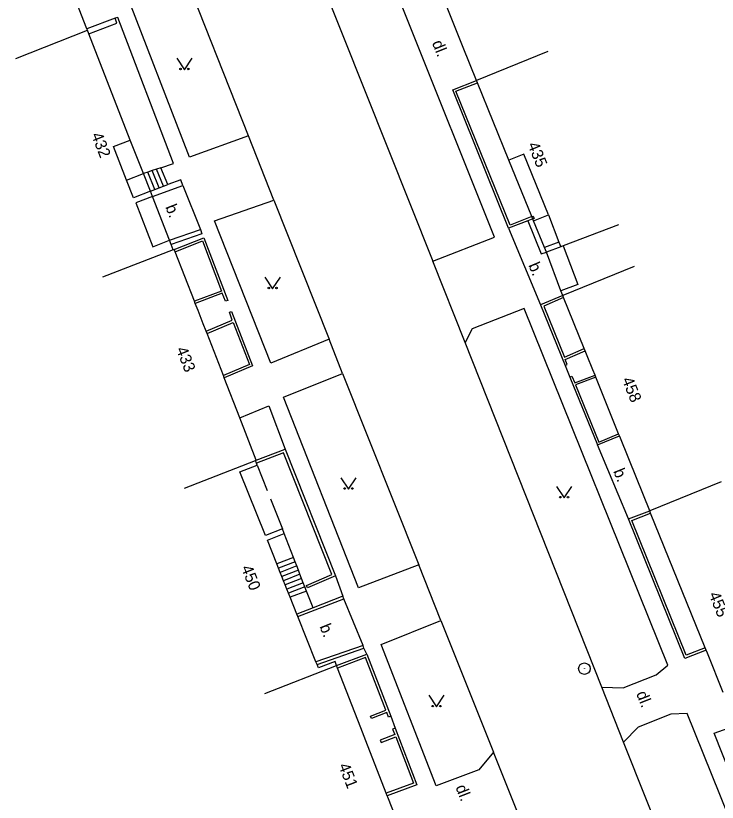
# Model space of a CAD drawing. Extents: x -577457 to -568404, y -1208466 to -1201387.
# Drawn here: x -575242.8 to -575197.2, y -1204609.6 to -1204558.5 of the extents above; entities that cross this region are included whole.
import ezdxf

# ---------------------------------------------------------------- set-up
doc = ezdxf.new("R2010")
doc.units = 0
for name, color, linetype in [('BUDOVY_MĚŘ', 7, 'Continuous'), ('MAP_ZN_BP', 7, 'Continuous'), ('POMOC_POPIS', 7, 'Continuous'), ('ROZHRANÍ_PLOCH', 7, 'Continuous'), ('ZN_DOPLŇKOVÉ', 7, 'Continuous'), ('ZN_KULTUR', 7, 'Continuous'), ('Č_POPIS_ORIENT', 7, 'Continuous')]:
    doc.layers.add(name, color=color, linetype=linetype)

msp = doc.modelspace()

# ---------------------------------------------------------------- linework, layer by layer
at = {"layer": 'BUDOVY_MĚŘ'}
for points in [[(-575238.17, -1204559.36), (-575238.83, -1204557.68)], [(-575242.79, -1204561.27), (-575238.14, -1204559.45)], [(-575238.14, -1204559.45), (-575238.17, -1204559.36)], [(-575238.05, -1204559.67), (-575238.14, -1204559.45)], [(-575235.35, -1204566.57), (-575238.05, -1204559.67)], [(-575212.88, -1204562.71), (-575213.74, -1204560.57)], [(-575208.25, -1204560.83), (-575212.88, -1204562.71)], [(-575212.82, -1204562.86), (-575212.88, -1204562.71)], [(-575210.78, -1204567.87), (-575212.82, -1204562.86)], [(-575234.5, -1204568.75), (-575235.35, -1204566.57)], [(-575209.28, -1204571.54), (-575210.78, -1204567.87)], [(-575234.05, -1204569.89), (-575234.5, -1204568.75)], [(-575233.92, -1204570.23), (-575234.05, -1204569.89)], [(-575232.8, -1204573.08), (-575233.92, -1204570.23)], [(-575209.22, -1204571.69), (-575209.28, -1204571.54)], [(-575209.17, -1204571.81), (-575209.22, -1204571.69)], [(-575208.47, -1204573.54), (-575209.17, -1204571.81)], [(-575203.66, -1204572.08), (-575207.24, -1204573.44)], [(-575232.69, -1204573.36), (-575232.8, -1204573.08)], [(-575232.56, -1204573.69), (-575232.69, -1204573.36)], [(-575207.24, -1204573.44), (-575207.41, -1204573.51)], [(-575232.56, -1204573.69), (-575237.16, -1204575.48)], [(-575232.5, -1204573.67), (-575232.56, -1204573.69)], [(-575232.44, -1204573.82), (-575232.5, -1204573.67)], [(-575231.19, -1204577.03), (-575232.44, -1204573.82)], [(-575208.34, -1204573.86), (-575208.47, -1204573.54)], [(-575207.41, -1204573.51), (-575208.34, -1204573.86)], [(-575207.39, -1204576.36), (-575208.34, -1204573.86)], [(-575202.64, -1204574.78), (-575207.28, -1204576.66)], [(-575207.28, -1204576.66), (-575207.39, -1204576.36)], [(-575231.13, -1204577.18), (-575231.19, -1204577.03)], [(-575207.22, -1204576.8), (-575207.28, -1204576.66)], [(-575205.88, -1204580.11), (-575207.22, -1204576.8)], [(-575230.95, -1204577.64), (-575231.13, -1204577.18)], [(-575230.43, -1204578.97), (-575230.62, -1204578.5)], [(-575230.37, -1204579.12), (-575230.43, -1204578.97)], [(-575229.31, -1204581.85), (-575230.37, -1204579.12)], [(-575205.82, -1204580.25), (-575205.88, -1204580.11)], [(-575205.69, -1204580.58), (-575205.82, -1204580.25)], [(-575205.18, -1204581.84), (-575205.32, -1204581.48)], [(-575229.25, -1204582), (-575229.31, -1204581.85)], [(-575205.13, -1204581.97), (-575205.18, -1204581.84)], [(-575203.65, -1204585.63), (-575205.13, -1204581.97)], [(-575227.17, -1204587.35), (-575228.24, -1204584.61)], [(-575203.59, -1204585.77), (-575203.65, -1204585.63)], [(-575203.53, -1204585.93), (-575203.59, -1204585.77)], [(-575231.83, -1204589.17), (-575227.23, -1204587.37)], [(-575225.48, -1204591.8), (-575226.58, -1204592.24), (-575228.23, -1204588.11), (-575227.11, -1204587.68)], [(-575227.23, -1204587.37), (-575227.17, -1204587.35)], [(-575227.16, -1204587.54), (-575227.23, -1204587.37)], [(-575227.11, -1204587.68), (-575227.16, -1204587.54)], [(-575201.63, -1204590.63), (-575202.49, -1204588.5)], [(-575196.99, -1204588.75), (-575201.63, -1204590.63)], [(-575201.57, -1204590.78), (-575201.63, -1204590.63)], [(-575198.03, -1204599.53), (-575201.57, -1204590.78)], [(-575225.36, -1204592.11), (-575225.48, -1204591.8)], [(-575225.84, -1204594.08), (-575226.45, -1204592.55), (-575225.36, -1204592.11)], [(-575225.73, -1204594.36), (-575225.84, -1204594.08)], [(-575225.62, -1204594.63), (-575225.73, -1204594.36)], [(-575225.52, -1204594.9), (-575225.62, -1204594.63)], [(-575225.41, -1204595.17), (-575225.52, -1204594.9)], [(-575225.3, -1204595.44), (-575225.41, -1204595.17)], [(-575225.19, -1204595.71), (-575225.3, -1204595.44)], [(-575225.08, -1204595.98), (-575225.19, -1204595.71)], [(-575224.97, -1204596.25), (-575225.08, -1204595.98)], [(-575224.53, -1204597.34), (-575224.97, -1204596.25)], [(-575224.47, -1204597.5), (-575224.53, -1204597.34)], [(-575197.96, -1204599.69), (-575198.03, -1204599.53)], [(-575197.88, -1204599.88), (-575197.96, -1204599.69)], [(-575223.23, -1204600.6), (-575223.3, -1204600.43)], [(-575221.96, -1204600.68), (-575222.06, -1204600.41), (-575223.14, -1204600.83), (-575223.23, -1204600.6)], [(-575226.62, -1204602.49), (-575221.96, -1204600.68)], [(-575221.9, -1204600.84), (-575221.96, -1204600.68)], [(-575220.39, -1204604.71), (-575221.9, -1204600.84)], [(-575218.73, -1204608.97), (-575220.06, -1204605.57)], [(-575218.67, -1204609.13), (-575218.73, -1204608.97)], [(-575218.63, -1204609.23), (-575218.67, -1204609.13)]]:
    msp.add_lwpolyline(points, dxfattribs=at)
at = {"layer": 'MAP_ZN_BP'}
for radius in [0.375, 0.0005]:
    msp.add_circle((-575205.87, -1204600.88), radius, dxfattribs=at)
at = {"layer": 'ROZHRANÍ_PLOCH'}
for points in [[(-575215.71, -1204574.44), (-575211.71, -1204572.88), (-575217.35, -1204558.78), (-575226.55, -1204535.73), (-575227.92, -1204533.66)], [(-575231.17, -1204535.5), (-575224.5, -1204552.39), (-575215.71, -1204574.44)], [(-575227.68, -1204566.31), (-575231.5, -1204567.69), (-575235.77, -1204556.62), (-575232.12, -1204555.08)], [(-575227.68, -1204566.31), (-575232.12, -1204555.08)], [(-575233.36, -1204568.37), (-575232.54, -1204568.1), (-575236.16, -1204558.62), (-575236.33, -1204558.67)], [(-575226.03, -1204570.47), (-575227.68, -1204566.31)], [(-575233.36, -1204568.37), (-575233.64, -1204568.46)], [(-575232.91, -1204569.46), (-575233.36, -1204568.37)], [(-575234.21, -1204568.65), (-575234.5, -1204568.75)], [(-575233.93, -1204568.56), (-575234.21, -1204568.65)], [(-575233.75, -1204569.78), (-575234.21, -1204568.65)], [(-575233.64, -1204568.46), (-575233.93, -1204568.56)], [(-575233.47, -1204569.67), (-575233.93, -1204568.56)], [(-575233.19, -1204569.57), (-575233.64, -1204568.46)], [(-575234.05, -1204569.89), (-575233.75, -1204569.78)], [(-575233.75, -1204569.78), (-575233.47, -1204569.67)], [(-575233.47, -1204569.67), (-575233.19, -1204569.57)], [(-575233.19, -1204569.57), (-575232.91, -1204569.46)], [(-575231.95, -1204569.52), (-575230.8, -1204572.37)], [(-575222.43, -1204579.5), (-575226.23, -1204581.06), (-575229.89, -1204571.82), (-575226.03, -1204570.47)], [(-575226.03, -1204570.47), (-575222.43, -1204579.5)], [(-575209.54, -1204571.81), (-575208.67, -1204573.95), (-575208.34, -1204573.86)], [(-575210.79, -1204572.29), (-575208.71, -1204577.27)], [(-575213.61, -1204579.72), (-575215.71, -1204574.44)], [(-575204.74, -1204602.07), (-575203.36, -1204602.12), (-575201.22, -1204601.27), (-575200.45, -1204600.65), (-575209.79, -1204577.5), (-575213.16, -1204578.82), (-575213.61, -1204579.72)], [(-575221.57, -1204581.73), (-575222.43, -1204579.5)], [(-575204.74, -1204602.07), (-575213.61, -1204579.72)], [(-575216.61, -1204594.14), (-575220.54, -1204595.64), (-575225.41, -1204583.25), (-575221.57, -1204581.73)], [(-575221.57, -1204581.73), (-575216.61, -1204594.14)], [(-575228.24, -1204584.61), (-575226.35, -1204583.82), (-575225.3, -1204586.64)], [(-575203.01, -1204591.16), (-575205.01, -1204586.36)], [(-575227.11, -1204587.68), (-575226.46, -1204589.32)], [(-575226.25, -1204589.86), (-575225.48, -1204591.8)], [(-575224.76, -1204593.66), (-575225.36, -1204592.11)], [(-575224.76, -1204593.66), (-575225.84, -1204594.08)], [(-575224.65, -1204593.94), (-575224.76, -1204593.66)], [(-575224.65, -1204593.94), (-575225.73, -1204594.36)], [(-575224.55, -1204594.21), (-575225.62, -1204594.63)], [(-575224.55, -1204594.21), (-575224.65, -1204593.94)], [(-575224.44, -1204594.48), (-575224.55, -1204594.21)], [(-575215.19, -1204597.75), (-575216.61, -1204594.14)], [(-575224.44, -1204594.48), (-575225.52, -1204594.9)], [(-575224.34, -1204594.75), (-575225.41, -1204595.17)], [(-575224.34, -1204594.75), (-575224.44, -1204594.48)], [(-575224.23, -1204595.02), (-575224.34, -1204594.75)], [(-575222.04, -1204594.85), (-575221.56, -1204596.18)], [(-575224.23, -1204595.02), (-575225.3, -1204595.44)], [(-575224.12, -1204595.3), (-575225.19, -1204595.71)], [(-575224.12, -1204595.3), (-575224.23, -1204595.02)], [(-575224.02, -1204595.57), (-575224.12, -1204595.3)], [(-575224.02, -1204595.57), (-575225.08, -1204595.98)], [(-575223.91, -1204595.84), (-575224.97, -1204596.25)], [(-575223.91, -1204595.84), (-575224.02, -1204595.57)], [(-575223.49, -1204596.93), (-575223.91, -1204595.84)], [(-575220.24, -1204599.38), (-575221.49, -1204596.35)], [(-575211.78, -1204606.3), (-575212.73, -1204607.45), (-575215.49, -1204608.49), (-575219.07, -1204599.32), (-575215.19, -1204597.75)], [(-575215.19, -1204597.75), (-575211.78, -1204606.3)], [(-575220, -1204599.93), (-575220.18, -1204599.55)], [(-575203.33, -1204605.65), (-575204.74, -1204602.07)], [(-575194.92, -1204614.42), (-575199.19, -1204603.8), (-575200.25, -1204603.84), (-575202.37, -1204604.68), (-575203.33, -1204605.65)], [(-575192.89, -1204631.84), (-575203.33, -1204605.65)], [(-575210.25, -1204610.08), (-575211.78, -1204606.3)]]:
    msp.add_lwpolyline(points, dxfattribs=at)
at = {"layer": 'ZN_DOPLŇKOVÉ'}
for points in [[(-575213.74, -1204560.57), (-575214.78, -1204557.97)], [(-575236.33, -1204558.67), (-575238.17, -1204559.36)], [(-575238.05, -1204559.67), (-575236.22, -1204558.98), (-575236.33, -1204558.67)], [(-575210.79, -1204572.29), (-575214.42, -1204563.32), (-575212.88, -1204562.71)], [(-575209.28, -1204571.54), (-575210.7, -1204572.09), (-575214.21, -1204563.41), (-575212.82, -1204562.86)], [(-575235.6, -1204569.18), (-575236.45, -1204567), (-575235.35, -1204566.57)], [(-575208.2, -1204571.42), (-575209.81, -1204567.48), (-575210.78, -1204567.87)], [(-575235.6, -1204569.18), (-575234.5, -1204568.75)], [(-575234.05, -1204569.89), (-575235.15, -1204570.32), (-575235.6, -1204569.18)], [(-575231.95, -1204569.52), (-575232.08, -1204569.16), (-575232.91, -1204569.46)], [(-575233.92, -1204570.23), (-575231.95, -1204569.52)], [(-575233.92, -1204570.23), (-575235, -1204570.65), (-575233.88, -1204573.5), (-575232.8, -1204573.08)], [(-575209.17, -1204571.81), (-575208.2, -1204571.42)], [(-575208.2, -1204571.42), (-575207.53, -1204573.19)], [(-575209.54, -1204571.81), (-575210.79, -1204572.29)], [(-575209.22, -1204571.69), (-575209.54, -1204571.81)], [(-575209.28, -1204571.54), (-575209.2, -1204571.51), (-575209.14, -1204571.66), (-575209.22, -1204571.69)], [(-575232.8, -1204573.08), (-575230.8, -1204572.37)], [(-575230.8, -1204572.37), (-575230.7, -1204572.65), (-575232.69, -1204573.36)], [(-575232.5, -1204573.67), (-575230.57, -1204572.92), (-575229.03, -1204576.98), (-575229.18, -1204577.03), (-575229.38, -1204576.52), (-575231.13, -1204577.18)], [(-575232.44, -1204573.82), (-575230.67, -1204573.12), (-575229.43, -1204576.37), (-575231.19, -1204577.03)], [(-575207.53, -1204573.19), (-575208.47, -1204573.54)], [(-575207.53, -1204573.19), (-575207.41, -1204573.51)], [(-575207.24, -1204573.44), (-575206.29, -1204575.94), (-575207.39, -1204576.36)], [(-575207.28, -1204576.66), (-575208.71, -1204577.27)], [(-575207.22, -1204576.8), (-575208.51, -1204577.35), (-575207.17, -1204580.67), (-575205.88, -1204580.11)], [(-575208.71, -1204577.27), (-575207.12, -1204581.2)], [(-575230.62, -1204578.5), (-575230.95, -1204577.64)], [(-575230.43, -1204578.97), (-575228.73, -1204578.26), (-575228.92, -1204577.74), (-575228.78, -1204577.69), (-575227.42, -1204581.23), (-575229.25, -1204582)], [(-575230.37, -1204579.12), (-575228.67, -1204578.41), (-575227.62, -1204581.14), (-575229.31, -1204581.85)], [(-575207.12, -1204581.2), (-575206.98, -1204581.14), (-575207.12, -1204580.81), (-575205.82, -1204580.25)], [(-575205.32, -1204581.48), (-575205.69, -1204580.58)], [(-575207.12, -1204581.2), (-575206.81, -1204581.96)], [(-575228.24, -1204584.61), (-575229.25, -1204582)], [(-575206.81, -1204581.96), (-575206.68, -1204581.9), (-575206.5, -1204582.33), (-575205.18, -1204581.84)], [(-575206.81, -1204581.96), (-575205.01, -1204586.36)], [(-575205.13, -1204581.97), (-575206.44, -1204582.47), (-575204.93, -1204586.17), (-575203.65, -1204585.63)], [(-575205.01, -1204586.36), (-575203.59, -1204585.77)], [(-575202.49, -1204588.5), (-575203.53, -1204585.93)], [(-575227.17, -1204587.35), (-575225.3, -1204586.64)], [(-575225.3, -1204586.64), (-575222.04, -1204594.85)], [(-575222.04, -1204594.85), (-575223.84, -1204595.64), (-575223.91, -1204595.48), (-575222.27, -1204594.76), (-575225.4, -1204586.87), (-575227.16, -1204587.54)], [(-575203.01, -1204591.16), (-575201.63, -1204590.63)], [(-575198.03, -1204599.53), (-575199.26, -1204600.01), (-575202.79, -1204591.26), (-575201.57, -1204590.78)], [(-575197.96, -1204599.69), (-575199.36, -1204600.23), (-575203.01, -1204591.16)], [(-575224.47, -1204597.5), (-575221.49, -1204596.35)], [(-575221.56, -1204596.18), (-575223.49, -1204596.93)], [(-575221.49, -1204596.35), (-575221.56, -1204596.18)], [(-575223.49, -1204596.93), (-575224.53, -1204597.34)], [(-575223.3, -1204600.43), (-575224.47, -1204597.5)], [(-575220.24, -1204599.38), (-575223.3, -1204600.43)], [(-575220.18, -1204599.55), (-575220.24, -1204599.38)], [(-575223.23, -1204600.6), (-575220.18, -1204599.55)], [(-575221.96, -1204600.68), (-575220, -1204599.93)], [(-575220, -1204599.93), (-575218.43, -1204603.96)], [(-575196.86, -1204602.42), (-575197.88, -1204599.88)], [(-575219.75, -1204603.96), (-575218.76, -1204603.58), (-575220.09, -1204600.15), (-575221.9, -1204600.84)], [(-575218.69, -1204603.73), (-575219.69, -1204604.12), (-575219.75, -1204603.96)], [(-575218.43, -1204603.96), (-575218.59, -1204604.02), (-575218.69, -1204603.73)], [(-575218.43, -1204603.96), (-575218.16, -1204604.74)], [(-575192.43, -1204613.5), (-575193.87, -1204614.06), (-575197.44, -1204605.07), (-575196, -1204604.54)], [(-575220.06, -1204605.57), (-575220.39, -1204604.71)], [(-575218.16, -1204604.74), (-575216.75, -1204608.42), (-575218.67, -1204609.13)], [(-575218.16, -1204604.74), (-575218.32, -1204604.8), (-575218.18, -1204605.15)], [(-575218.18, -1204605.15), (-575219.13, -1204605.51), (-575219.07, -1204605.67)], [(-575219.07, -1204605.67), (-575218.12, -1204605.31), (-575216.97, -1204608.32), (-575218.73, -1204608.97)], [(-575217.64, -1204611.76), (-575218.63, -1204609.23)]]:
    msp.add_lwpolyline(points, dxfattribs=at)
at = {"layer": 'ZN_KULTUR'}
for points in [[(-575232.34, -1204561.26), (-575231.84, -1204562.01), (-575231.34, -1204561.26)], [(-575226.61, -1204575.48), (-575226.11, -1204576.23), (-575225.61, -1204575.48)], [(-575221.69, -1204588.49), (-575221.19, -1204589.24), (-575220.69, -1204588.49)], [(-575207.69, -1204589.05), (-575207.19, -1204589.8), (-575206.69, -1204589.05)], [(-575215.97, -1204602.61), (-575215.47, -1204603.36), (-575214.97, -1204602.61)]]:
    msp.add_lwpolyline(points, dxfattribs=at)
for centre in [(-575232.09, -1204561.96), (-575231.59, -1204561.96), (-575226.36, -1204576.18), (-575225.86, -1204576.18), (-575221.44, -1204589.19), (-575220.94, -1204589.19), (-575207.44, -1204589.75), (-575206.94, -1204589.75), (-575215.72, -1204603.31), (-575215.22, -1204603.31)]:
    msp.add_circle(centre, 0.05, dxfattribs=at)

# ---------------------------------------------------------------- texts
at = {"layer": 'POMOC_POPIS'}
for s, rotation, p in [('dl.', 291.82, (-575215.78, -1204560.26)), ('b.', 291.38, (-575233.09, -1204570.91)), ('b.', 292.77, (-575209.52, -1204574.69)), ('b.', 292.01, (-575204.01, -1204588.06)), ('b.', 291.78, (-575223.08, -1204598.14)), ('dl.', 291.49, (-575202.52, -1204602.49)), ('dl.', 291.29, (-575214.25, -1204608.57))]:
    msp.add_text(s, height=0.75, rotation=rotation, dxfattribs=at).set_placement(p)
at = {"layer": 'Č_POPIS_ORIENT'}
for s, rotation, p in [('432', 291.38, (-575237.9, -1204566.24)), ('435', 292.18, (-575209.57, -1204566.87)), ('433', 291.27, (-575232.39, -1204580.15)), ('458', 292.01, (-575203.45, -1204582.12)), ('450', 291.78, (-575228.17, -1204594.33)), ('455', 292.02, (-575197.81, -1204596.06)), ('451', 291.29, (-575221.85, -1204607.17))]:
    msp.add_text(s, height=0.75, rotation=rotation, dxfattribs=at).set_placement(p)

doc.saveas('drawing.dxf')
